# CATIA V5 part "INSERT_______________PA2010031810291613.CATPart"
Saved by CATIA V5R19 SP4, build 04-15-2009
Part number: INSERT_______________PA2010031810291613
Bounding box of the stored display mesh (mm): x -2.499 to 2.499, y -2.5 to 2.5, z -6 to 0
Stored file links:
  E:\CadInnWork\1\INSERT_______________PA2010031810291613.CATPart
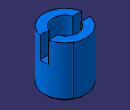
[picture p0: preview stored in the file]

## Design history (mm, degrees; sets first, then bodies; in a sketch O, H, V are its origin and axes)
Parameters
  Update = false
  PDM_version = "A"
  PDM_iteration = 1
  PDM_owner = "moren                    "
  PDM_comment = ""
  PDM_partnumber = "PA002170EA6A57201003181029160013"
Body1 (main body)
  Sketch1 on yz-plane, origin (0, 0, 0), H (0, 1, 0), V (0, 0, 1)
    axis line L1 (0, 68.5939) -> (0, -92.8528)
    point P1 (0, 68.5939)
    line L2 (0, 0) -> (2.5, 0)
    line L3 (2.5, 0) -> (2.5, -6)
    line L4 (2.5, -6) -> (0, -6)
    point P5 (0, -6)
    "Radius" L3 L1 = 2.5
    length L3 = 6
    coincidence: P1 V, P5 V
    vertical: L1 V, L3 V
    horizontal: L2 H, L4 H
  Shaft1: profile Sketch1, axis Sketch1.L1, angle 360
  Chamfer1: length 0.25, angle 45, on face of Shaft1 from Sketch1.L4
  Sketch2 on face of Shaft1 from Sketch1.L2, origin (0.3635, 1.8087, 0), H (1, 0, 0), V (0, 1, 0)
    point P1 (-0.3635, -1.8087)
    reference projected circle E1 centre (-0.3635, -1.8087) radius 2.5 from edge [face of Shaft1 from Sketch1.L2 | face of Shaft1 from Sketch1.L3]
    concentricity: E1 P1
  Hole1: placed by Sketch2, at (0, 0, 0) direction (0, 0, -1), diameter 3, through (limit type 3)
  Sketch3 on face of Shaft1 from Sketch1.L2, origin (0, 0, 0), H (1, 0, 0), V (0, 1, 0)
    line L1 (-3.4085, 0.5) -> (3.4085, 0.5)
    line L2 (3.4085, 0.5) -> (3.4085, -0.5)
    line L3 (3.4085, -0.5) -> (-3.4085, -0.5)
    line L4 (-3.4085, -0.5) -> (-3.4085, 0.5)
    reference intersected line E1 through (0, 0) direction (-1, 0) from zx-plane
    reference intersected line E2 through (0, 0) direction (0, 1) from yz-plane
    distance L1 L3 = 1
    horizontal: L1 H, L3 H
    vertical: L2 V, L4 V
    symmetry: L3 L1 E1, L2 L4 E2
  Pocket1: profile Sketch3, direction (0, 0, -1), length 2.5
